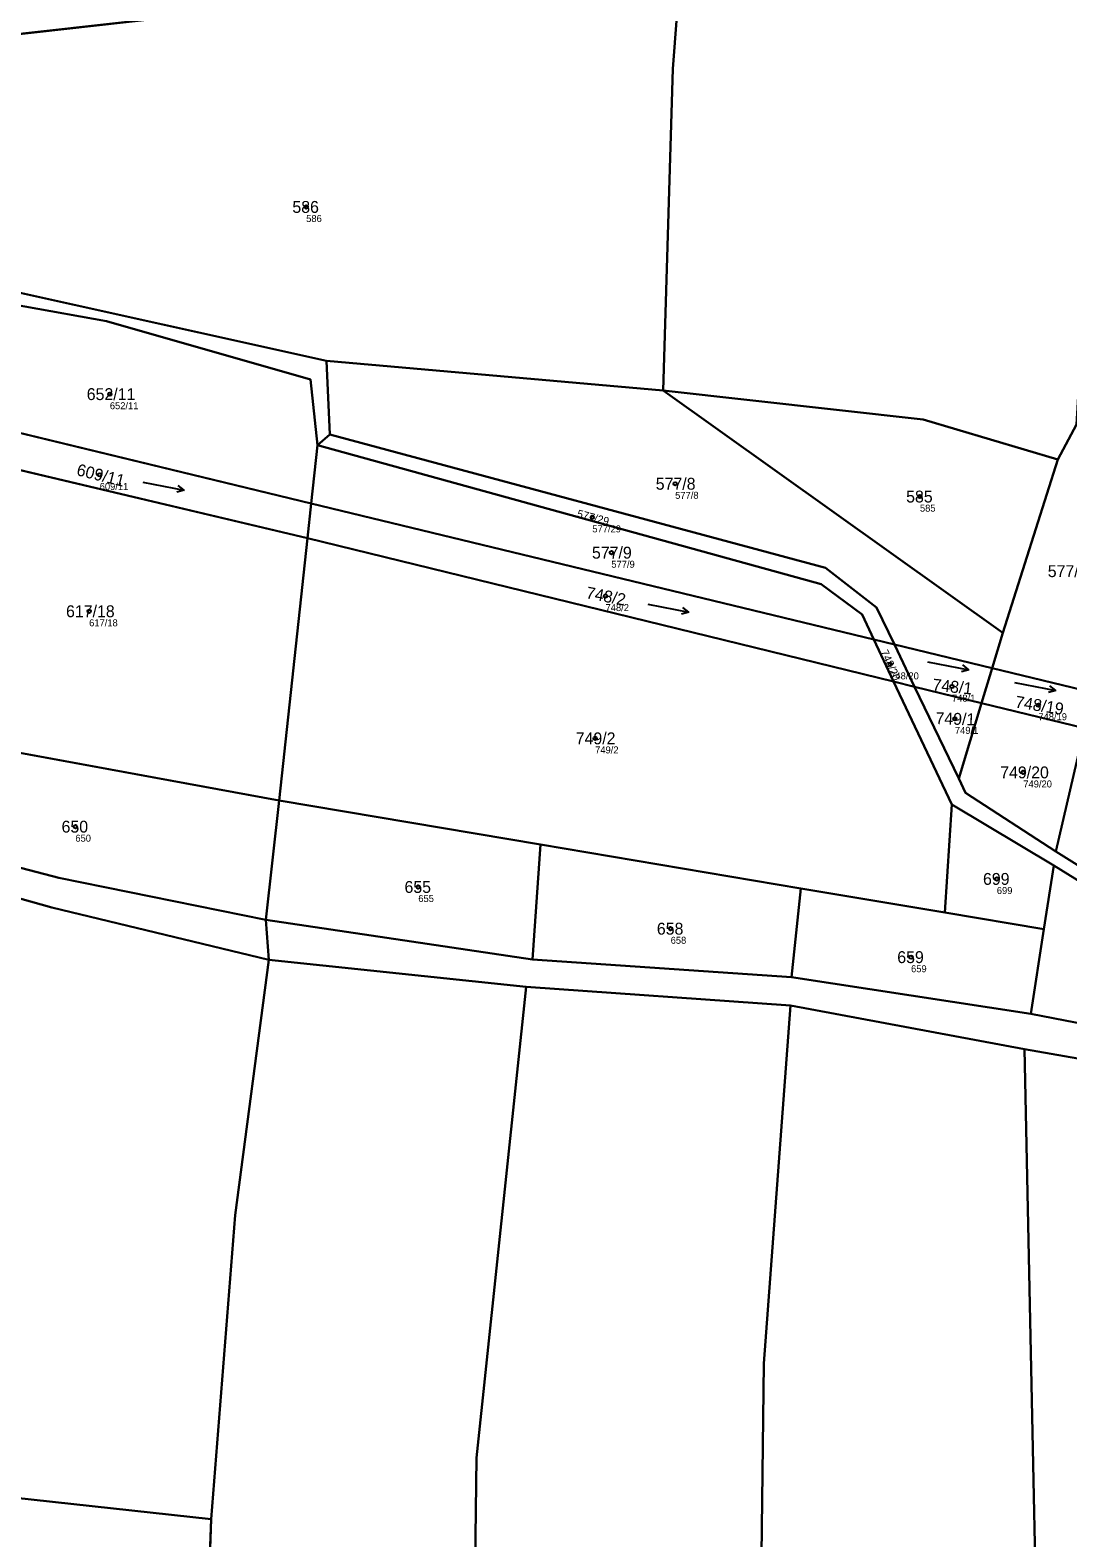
# Model space of a CAD drawing. Extents: x -767985 to -763816, y -1059600 to -1057360.
# Drawn here: x -764849.6 to -764701.2, y -1059284.4 to -1059068.8 of the extents above; entities that cross this region are included whole.
import ezdxf

# ---------------------------------------------------------------- set-up
doc = ezdxf.new("R2010")
doc.units = 0
for name, color, linetype in [('Definiční body', 7, 'Continuous'), ('Hranice parcel', 7, 'Continuous'), ('Parcelní čísla', 7, 'Continuous'), ('Polygon parcely', 7, 'Continuous'), ('Značky kultur', 7, 'Continuous')]:
    doc.layers.add(name, color=color, linetype=linetype)

msp = doc.modelspace()

# ---------------------------------------------------------------- linework, layer by layer
at = {"layer": 'Definiční body'}
for centre in [(-764810.14, -1059094.04994), (-764838.21, -1059120.82994), (-764839.66, -1059132.37994), (-764757.39, -1059133.64994), (-764722.39, -1059135.47994), (-764769.23, -1059138.44994), (-764766.51, -1059143.50994), (-764767.34, -1059149.70994), (-764841.17, -1059151.88994), (-764726.64, -1059159.47994), (-764717.81, -1059162.65994), (-764705.46, -1059165.31994), (-764717.39, -1059167.26994), (-764768.83, -1059170.06994), (-764707.61, -1059174.93994), (-764843.14, -1059182.69994), (-764711.4, -1059190.17994), (-764794.11, -1059191.32994), (-764758.03, -1059197.29994), (-764723.66, -1059201.36994)]:
    msp.add_circle(centre, 0.25, dxfattribs=at)
at = {"layer": 'Hranice parcel'}
for p, q in [((-764756.52, -1059058.65), (-764884.29, -1059073.04)), ((-764807.24, -1059116.05), (-764861.6, -1059104.01)), ((-764759.08, -1059120.3), (-764807.24, -1059116.05)), ((-764806.78, -1059126.58), (-764807.24, -1059116.05)), ((-764710.55, -1059154.97), (-764759.08, -1059120.3)), ((-764809.41, -1059136.46), (-764864.39, -1059123.15)), ((-764700.02, -1059125.18), (-764702.69, -1059130.2)), ((-764865.1, -1059128.36), (-764809.95, -1059141.41)), ((-764808.5, -1059128.14), (-764809.41, -1059136.46)), ((-764808.5, -1059128.14), (-764806.78, -1059126.58)), ((-764702.69, -1059130.2), (-764710.55, -1059154.97)), ((-764809.95, -1059141.41), (-764809.41, -1059136.46)), ((-764809.41, -1059136.46), (-764728.96, -1059155.93)), ((-764814.01, -1059178.97), (-764809.95, -1059141.41)), ((-764809.95, -1059141.41), (-764726.15, -1059161.95)), ((-764728.96, -1059155.93), (-764726.05, -1059156.63)), ((-764726.15, -1059161.95), (-764728.96, -1059155.93)), ((-764712.07, -1059160.01), (-764710.55, -1059154.97)), ((-764726.05, -1059156.63), (-764712.07, -1059160.01)), ((-764726.05, -1059156.63), (-764723.15, -1059162.68)), ((-764713.59, -1059165.02), (-764712.07, -1059160.01)), ((-764712.07, -1059160.01), (-764697.68, -1059163.49)), ((-764726.15, -1059161.95), (-764723.15, -1059162.68)), ((-764717.82, -1059179.52), (-764726.15, -1059161.95)), ((-764723.15, -1059162.68), (-764713.59, -1059165.02)), ((-764723.15, -1059162.68), (-764716.85, -1059175.82)), ((-764716.85, -1059175.82), (-764713.59, -1059165.02)), ((-764713.59, -1059165.02), (-764698.87, -1059168.63)), ((-764870.58, -1059168.56), (-764814.01, -1059178.97)), ((-764698.87, -1059168.63), (-764702.96, -1059186.26)), ((-764815.93, -1059196.03), (-764814.01, -1059178.97)), ((-764776.66, -1059185.26), (-764814.01, -1059178.97)), ((-764717.82, -1059179.52), (-764718.82, -1059194.99)), ((-764703.27, -1059188.28), (-764717.82, -1059179.52)), ((-764777.76, -1059201.7), (-764776.66, -1059185.26)), ((-764739.4, -1059191.53), (-764776.66, -1059185.26)), ((-764691.24, -1059193.61), (-764702.96, -1059186.26)), ((-764704.68, -1059197.37), (-764703.27, -1059188.28)), ((-764740.77, -1059204.21), (-764739.4, -1059191.53)), ((-764718.82, -1059194.99), (-764739.4, -1059191.53)), ((-764704.68, -1059197.37), (-764718.82, -1059194.99)), ((-764815.46, -1059201.74), (-764815.93, -1059196.03)), ((-764815.93, -1059196.03), (-764777.76, -1059201.7)), ((-764706.55, -1059209.46), (-764704.68, -1059197.37)), ((-764778.67, -1059205.63), (-764815.46, -1059201.74)), ((-764777.76, -1059201.7), (-764740.77, -1059204.21)), ((-764740.92, -1059208.29), (-764778.67, -1059205.63)), ((-764740.77, -1059204.21), (-764706.55, -1059209.46)), ((-764707.42, -1059214.53), (-764740.92, -1059208.29)), ((-764706.55, -1059209.46), (-764658.86, -1059218.75)), ((-764824.88, -1059315.59), (-764823.73, -1059281.76))]:
    msp.add_line(p, q, dxfattribs=at)
for points in [[(-764756.52, -1059058.65), (-764757.7, -1059074.31), (-764759.08, -1059120.3)], [(-764862.08, -1059106.19), (-764838.7, -1059110.37), (-764809.54, -1059118.72), (-764808.5, -1059128.14)], [(-764759.08, -1059120.3), (-764721.92, -1059124.44), (-764702.69, -1059130.2)], [(-764728.96, -1059155.93), (-764730.63, -1059152.36), (-764736.49, -1059148), (-764808.5, -1059128.14)], [(-764806.78, -1059126.58), (-764735.91, -1059145.69), (-764728.58, -1059151.36), (-764726.05, -1059156.63)], [(-764942.47, -1059160.99), (-764909.95, -1059174.57), (-764871.48, -1059187.27), (-764846.5, -1059194.25), (-764815.46, -1059201.74)], [(-764702.96, -1059186.26), (-764715.87, -1059177.87), (-764716.85, -1059175.82)], [(-764815.93, -1059196.03), (-764845.49, -1059190.02), (-764872.39, -1059183.02)], [(-764657.2, -1059208.32), (-764689.85, -1059196.56), (-764703.27, -1059188.28)], [(-764823.73, -1059281.76), (-764820.28, -1059238.28), (-764815.46, -1059201.74)], [(-764787.27, -1059389.7), (-764785.79, -1059273), (-764778.67, -1059205.63)], [(-764746.26, -1059388.66), (-764744.72, -1059259.5), (-764740.92, -1059208.29)], [(-764706.52, -1059387.29), (-764704.63, -1059349.3), (-764707.42, -1059214.53)], [(-764629.14, -1059225.48), (-764653.51, -1059223.97), (-764707.42, -1059214.53)], [(-764823.73, -1059281.76), (-764897.51, -1059273.71), (-764960.13, -1059271.45)]]:
    msp.add_lwpolyline(points, dxfattribs=at)
at = {"layer": 'Polygon parcely'}
for points in [[(-764748.11, -1059013.19), (-764749.81, -1059022.37), (-764752.02, -1059034.29), (-764756.52, -1059058.65), (-764757.7, -1059074.31), (-764759.08, -1059120.3), (-764721.92, -1059124.44), (-764702.69, -1059130.2), (-764700.02, -1059125.18), (-764698.56, -1059101.24), (-764697.02, -1059071.13), (-764692.07, -1059028.92), (-764686.12, -1058988.7), (-764671.11, -1058955.98), (-764663.89, -1058913.48), (-764656.11, -1058892.9), (-764725.9, -1058866.15), (-764734.33, -1058914), (-764735.1, -1058926.49), (-764735.34, -1058930.33), (-764737.47, -1058965.18), (-764739.22, -1058976.45)], [(-764966.27, -1059062.57), (-765060.07, -1059031.27), (-765151.17, -1058992.96), (-765171.68, -1058981.24), (-765190.33, -1058964.43), (-765190.34, -1058968.18), (-765173.39, -1058982.83), (-765152.48, -1058995.15), (-765060.83, -1059032.86), (-764967.66, -1059064.11), (-764918.75, -1059085.08), (-764895.84, -1059090.69), (-764862.08, -1059106.19), (-764838.7, -1059110.37), (-764809.54, -1059118.72), (-764808.5, -1059128.14), (-764806.78, -1059126.58), (-764807.24, -1059116.05), (-764861.6, -1059104.01), (-764892.8, -1059089.65), (-764906.25, -1059086.6), (-764918.06, -1059083.43)], [(-764752.02, -1059034.29), (-764758.51, -1059035.68), (-764764.34, -1059049.21), (-764818.31, -1059061.96), (-764833.85, -1059056.84), (-764858.96, -1059063.02), (-764885.92, -1059065.02), (-764927.24, -1059059.28), (-764957.74, -1059052.39), (-764966.27, -1059062.57), (-764918.06, -1059083.43), (-764906.25, -1059086.6), (-764904.96, -1059075.37), (-764884.29, -1059073.04), (-764756.52, -1059058.65)], [(-764862.38, -1059094.9), (-764861.6, -1059104.01), (-764807.24, -1059116.05), (-764759.08, -1059120.3), (-764757.7, -1059074.31), (-764756.52, -1059058.65), (-764884.29, -1059073.04), (-764886.5, -1059084.66)], [(-764940.29, -1059158.74), (-764968.04, -1059147.17), (-764996.73, -1059133.21), (-765012.05, -1059124.66), (-765078.11, -1059082.38), (-765079.83, -1059086.87), (-765045.15, -1059110.12), (-765001.55, -1059136.08), (-764969.08, -1059151.21), (-764945.3, -1059159.91), (-764942.47, -1059160.99), (-764909.95, -1059174.57), (-764871.48, -1059187.27), (-764846.5, -1059194.25), (-764815.46, -1059201.74), (-764815.93, -1059196.03), (-764845.49, -1059190.02), (-764872.39, -1059183.02), (-764905.79, -1059172.81)], [(-764808.5, -1059128.14), (-764809.54, -1059118.72), (-764838.7, -1059110.37), (-764862.08, -1059106.19), (-764864.39, -1059123.15), (-764809.41, -1059136.46)], [(-764759.08, -1059120.3), (-764807.24, -1059116.05), (-764806.78, -1059126.58), (-764735.91, -1059145.69), (-764728.58, -1059151.36), (-764726.05, -1059156.63), (-764712.07, -1059160.01), (-764710.55, -1059154.97)], [(-764759.08, -1059120.3), (-764710.55, -1059154.97), (-764702.69, -1059130.2), (-764721.92, -1059124.44)], [(-764809.41, -1059136.46), (-764864.39, -1059123.15), (-764865.1, -1059128.36), (-764809.95, -1059141.41)], [(-764702.69, -1059130.2), (-764710.55, -1059154.97), (-764712.07, -1059160.01), (-764697.68, -1059163.49), (-764689.03, -1059126.2), (-764700.02, -1059125.18)], [(-764814.01, -1059178.97), (-764809.95, -1059141.41), (-764865.1, -1059128.36), (-764870.58, -1059168.56)], [(-764809.41, -1059136.46), (-764728.96, -1059155.93), (-764730.63, -1059152.36), (-764736.49, -1059148), (-764808.5, -1059128.14)], [(-764726.05, -1059156.63), (-764728.58, -1059151.36), (-764735.91, -1059145.69), (-764806.78, -1059126.58), (-764808.5, -1059128.14), (-764736.49, -1059148), (-764730.63, -1059152.36), (-764728.96, -1059155.93)], [(-764726.15, -1059161.95), (-764728.96, -1059155.93), (-764809.41, -1059136.46), (-764809.95, -1059141.41)], [(-764717.82, -1059179.52), (-764726.15, -1059161.95), (-764809.95, -1059141.41), (-764814.01, -1059178.97), (-764776.66, -1059185.26), (-764739.4, -1059191.53), (-764718.82, -1059194.99)], [(-764723.15, -1059162.68), (-764726.05, -1059156.63), (-764728.96, -1059155.93), (-764726.15, -1059161.95)], [(-764713.59, -1059165.02), (-764712.07, -1059160.01), (-764726.05, -1059156.63), (-764723.15, -1059162.68)], [(-764698.87, -1059168.63), (-764697.68, -1059163.49), (-764712.07, -1059160.01), (-764713.59, -1059165.02)], [(-764820.28, -1059238.28), (-764815.46, -1059201.74), (-764846.5, -1059194.25), (-764871.48, -1059187.27), (-764909.95, -1059174.57), (-764942.47, -1059160.99), (-764954.01, -1059228.12), (-764960.13, -1059271.45), (-764897.51, -1059273.71), (-764823.73, -1059281.76)], [(-764716.85, -1059175.82), (-764713.59, -1059165.02), (-764723.15, -1059162.68)], [(-764698.87, -1059168.63), (-764713.59, -1059165.02), (-764716.85, -1059175.82), (-764715.87, -1059177.87), (-764702.96, -1059186.26)], [(-764815.93, -1059196.03), (-764814.01, -1059178.97), (-764870.58, -1059168.56), (-764871.81, -1059177.56), (-764872.39, -1059183.02), (-764845.49, -1059190.02)], [(-764698.87, -1059168.63), (-764702.96, -1059186.26), (-764691.24, -1059193.61), (-764687.28, -1059171.47)], [(-764777.76, -1059201.7), (-764776.66, -1059185.26), (-764814.01, -1059178.97), (-764815.93, -1059196.03)], [(-764703.27, -1059188.28), (-764717.82, -1059179.52), (-764718.82, -1059194.99), (-764704.68, -1059197.37)], [(-764739.4, -1059191.53), (-764776.66, -1059185.26), (-764777.76, -1059201.7), (-764740.77, -1059204.21)], [(-764657.2, -1059208.32), (-764689.85, -1059196.56), (-764703.27, -1059188.28), (-764704.68, -1059197.37), (-764706.55, -1059209.46), (-764658.86, -1059218.75)], [(-764704.68, -1059197.37), (-764718.82, -1059194.99), (-764739.4, -1059191.53), (-764740.77, -1059204.21), (-764706.55, -1059209.46)], [(-764778.67, -1059205.63), (-764815.46, -1059201.74), (-764820.28, -1059238.28), (-764823.73, -1059281.76), (-764824.88, -1059315.59), (-764824.47, -1059382.24), (-764822.93, -1059392.66), (-764790.27, -1059389.78), (-764787.27, -1059389.7), (-764785.79, -1059273)], [(-764746.26, -1059388.66), (-764744.72, -1059259.5), (-764740.92, -1059208.29), (-764778.67, -1059205.63), (-764785.79, -1059273), (-764787.27, -1059389.7)], [(-764706.52, -1059387.29), (-764704.63, -1059349.3), (-764707.42, -1059214.53), (-764740.92, -1059208.29), (-764744.72, -1059259.5), (-764746.26, -1059388.66), (-764725.57, -1059388.13)], [(-764653.51, -1059223.97), (-764707.42, -1059214.53), (-764704.63, -1059349.3), (-764706.52, -1059387.29), (-764664.49, -1059385.45), (-764661.48, -1059343.79), (-764625.54, -1059342.27), (-764629.14, -1059225.48)], [(-764824.88, -1059315.59), (-764823.73, -1059281.76), (-764897.51, -1059273.71), (-764960.13, -1059271.45), (-764963.4, -1059271.33), (-764965.58, -1059302.41), (-764965.02, -1059316.8)]]:
    msp.add_lwpolyline(points, close=True, dxfattribs=at)
for points in [[(-764691.24, -1059193.61), (-764702.96, -1059186.26), (-764715.87, -1059177.87), (-764716.85, -1059175.82), (-764723.15, -1059162.68), (-764726.15, -1059161.95), (-764717.82, -1059179.52), (-764703.27, -1059188.28), (-764689.85, -1059196.56)], [(-764487.38, -1059220.24), (-764566.3, -1059221.83), (-764606.49, -1059221.61), (-764629.64, -1059222.47), (-764658.86, -1059218.75), (-764706.55, -1059209.46), (-764740.77, -1059204.21), (-764777.76, -1059201.7), (-764815.93, -1059196.03), (-764815.46, -1059201.74), (-764778.67, -1059205.63), (-764740.92, -1059208.29), (-764707.42, -1059214.53), (-764653.51, -1059223.97), (-764629.14, -1059225.48), (-764613.39, -1059224.32), (-764566.33, -1059225.21), (-764486.99, -1059223.34)]]:
    msp.add_lwpolyline(points, dxfattribs=at)
at = {"layer": 'Značky kultur'}
for p, q in [((-764833.49, -1059133.409), (-764827.6, -1059134.554)), ((-764827.6, -1059134.554), (-764828.655, -1059134.86)), ((-764827.6, -1059134.554), (-764828.463, -1059133.875)), ((-764761.31, -1059150.869), (-764755.42, -1059152.014)), ((-764755.42, -1059152.014), (-764756.475, -1059152.32)), ((-764755.42, -1059152.014), (-764756.283, -1059151.335)), ((-764721.3, -1059159.109), (-764715.41, -1059160.254)), ((-764715.41, -1059160.254), (-764716.465, -1059160.56)), ((-764715.41, -1059160.254), (-764716.273, -1059159.575)), ((-764708.86, -1059162.069), (-764702.97, -1059163.214)), ((-764702.97, -1059163.214), (-764703.833, -1059162.535)), ((-764702.97, -1059163.214), (-764704.025, -1059163.52))]:
    msp.add_line(p, q, dxfattribs=at)

# ---------------------------------------------------------------- texts
at = {"layer": 'Definiční body'}
for s, p in [('586', (-764810.14, -1059096.206)), ('652/11', (-764838.21, -1059122.986)), ('609/11', (-764839.66, -1059134.536)), ('577/8', (-764757.39, -1059135.806)), ('585', (-764722.39, -1059137.636)), ('577/29', (-764769.23, -1059140.606)), ('577/9', (-764766.51, -1059145.666)), ('748/2', (-764767.34, -1059151.866)), ('617/18', (-764841.17, -1059154.046)), ('748/20', (-764726.64, -1059161.636)), ('748/1', (-764717.81, -1059164.816)), ('748/19', (-764705.46, -1059167.476)), ('749/1', (-764717.39, -1059169.426)), ('749/2', (-764768.83, -1059172.226)), ('749/20', (-764707.61, -1059177.096)), ('650', (-764843.14, -1059184.856)), ('655', (-764794.11, -1059193.486)), ('699', (-764711.4, -1059192.336)), ('658', (-764758.03, -1059199.456)), ('659', (-764723.66, -1059203.526))]:
    msp.add_text(s, height=0.999996, dxfattribs=at).set_placement(p)
at = {"layer": 'Parcelní čísla'}
for s, p in [('586', (-764812.114, -1059094.9)), ('652/11', (-764841.515, -1059121.68)), ('577/8', (-764760.163, -1059134.5)), ('585', (-764724.364, -1059136.33)), ('577/9', (-764769.283, -1059144.36)), ('577/27', (-764704.115, -1059147)), ('617/18', (-764844.475, -1059152.74)), ('749/2', (-764771.603, -1059170.92)), ('749/20', (-764710.915, -1059175.79)), ('650', (-764845.114, -1059183.55)), ('655', (-764796.084, -1059192.18)), ('699', (-764713.374, -1059191.03)), ('658', (-764760.004, -1059198.15)), ('659', (-764725.634, -1059202.22))]:
    msp.add_text(s, height=1.699998, dxfattribs=at).set_placement(p)
for s, height, rotation, p in [('609/11', 1.699998, 346, (-764843.073, -1059132.405)), ('577/29', 1.14, 345, (-764771.518, -1059138.426)), ('748/2', 1.699998, 349, (-764770.224, -1059150.015)), ('748/20', 1.14, 294, (-764728.062, -1059157.686)), ('748/1', 1.699998, 354, (-764720.657, -1059163.215)), ('748/19', 1.699998, 351, (-764708.858, -1059165.642)), ('749/1', 1.699998, 358, (-764720.191, -1059168.022))]:
    msp.add_text(s, height=height, rotation=rotation, dxfattribs=at).set_placement(p)

doc.saveas('drawing.dxf')
